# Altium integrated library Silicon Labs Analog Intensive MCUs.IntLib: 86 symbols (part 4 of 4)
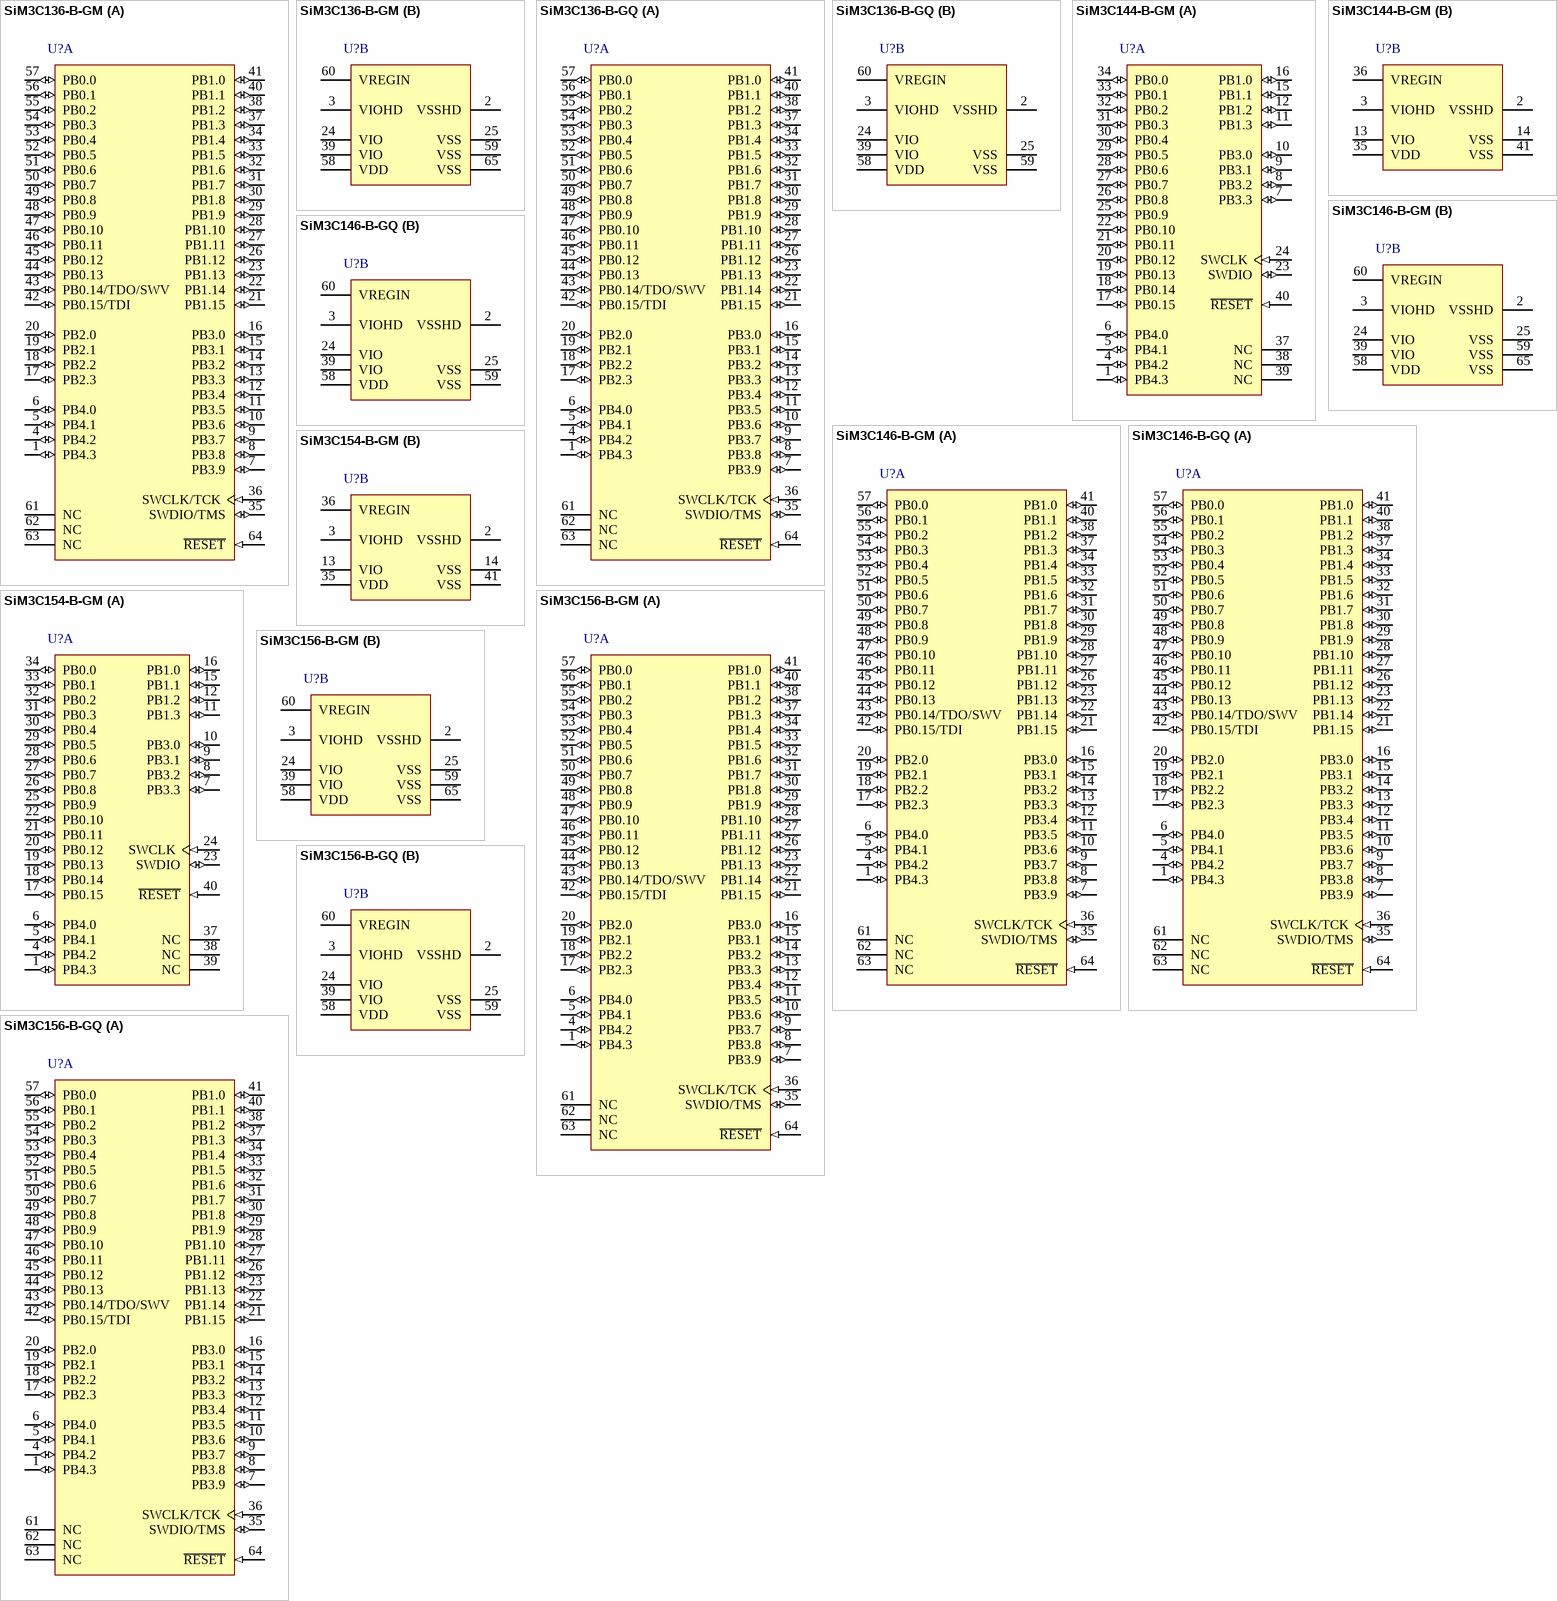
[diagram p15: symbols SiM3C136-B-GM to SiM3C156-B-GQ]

## SiM3C156-B-GM
designator U?
High-Performance, Low-Power, 32-Bit Precision32(TM) MCU Family, 80 MHz, 32 kB RAM, 128 kB Flash, -40 to 85 degC, 64-pin QFN; Manufacturer: Silicon Labs; PartNumber: SiM3C156-B-GM; ADC 1: 12-bit, 13-ch., 250 ksps; ADC 2: 12-bit, 15-ch., 250 ksps; AEC-Q100: FALSE; Comparators: 2; DAC: 10-bit, 2-ch.; Debug Interface: JTAG; SW; Dig I/O Pins: 50; Flash: 128 kB; Internal Osc. Accuracy: +/-1.5%; MCU Core: ARM Cortex-M3; MHz: 80; PCA Channels: 10; RAM: 32 kB; Temp Sensor: TRUE; Timers (16-bit): 4; Sub-Family: Analog Intensive MCUs
footprint SLAB-QFN-64-4100x4100TP_N (QFN, 64-Leads, Body 9x9mm, Pitch 0.5mm, Thermal Pad 4.1x4.1mm, IPC Medium Density)
footprint SLAB-QFN-64-4100x4100TP_L (QFN, 64-Leads, Body 9x9mm, Pitch 0.5mm, Thermal Pad 4.1x4.1mm, IPC High Density)
footprint SLAB-QFN-64-4100x4100TP_M (QFN, 64-Leads, Body 9x9mm, Pitch 0.5mm, Thermal Pad 4.1x4.1mm, IPC Low Density)
part A pins: 1 PB4.3 (io), 4 PB4.2 (io), 5 PB4.1 (io), 6 PB4.0 (io), 7 PB3.9 (io), 8 PB3.8 (io), 9 PB3.7 (io), 10 PB3.6 (io), 11 PB3.5 (io), 12 PB3.4 (io), 13 PB3.3 (io), 14 PB3.2 (io), 15 PB3.1 (io), 16 PB3.0 (io), 17 PB2.3 (io), 18 PB2.2 (io), 19 PB2.1 (io), 20 PB2.0 (io), 21 PB1.15 (io), 22 PB1.14 (io), 23 PB1.13 (io), 26 PB1.12 (io), 27 PB1.11 (io), 28 PB1.10 (io), 29 PB1.9 (io), 30 PB1.8 (io), 31 PB1.7 (io), 32 PB1.6 (io), 33 PB1.5 (io), 34 PB1.4 (io), 35 SWDIO/TMS (io), 36 SWCLK/TCK (in), 37 PB1.3 (io), 38 PB1.2 (io), 40 PB1.1 (io), 41 PB1.0 (io), 42 PB0.15/TDI (io), 43 PB0.14/TDO/SWV (io), 44 PB0.13 (io), 45 PB0.12 (io), 46 PB0.11 (io), 47 PB0.10 (io), 48 PB0.9 (io), 49 PB0.8 (io), 50 PB0.7 (io), 51 PB0.6 (io), 52 PB0.5 (io), 53 PB0.4 (io), 54 PB0.3 (io), 55 PB0.2 (io), 56 PB0.1 (io), 57 PB0.0 (io), 61 NC, 62 NC, 63 NC, 64 ~{RESET} (in)
part B pins: 2 VSSHD (power), 3 VIOHD (power), 24 VIO (power), 25 VSS (power), 39 VIO (power), 58 VDD (power), 59 VSS (power), 60 VREGIN (power), 65 VSS (power)

## SiM3C156-B-GQ
designator U?
High-Performance, Low-Power, 32-Bit Precision32(TM) MCU Family, 80 MHz, 32 kB RAM, 128 kB Flash, -40 to 85 degC, 64-pin QFP; Manufacturer: Silicon Labs; PartNumber: SiM3C156-B-GQ; ADC 1: 12-bit, 13-ch., 250 ksps; ADC 2: 12-bit, 15-ch., 250 ksps; AEC-Q100: FALSE; Comparators: 2; DAC: 10-bit, 2-ch.; Debug Interface: JTAG; SW; Dig I/O Pins: 50; Flash: 128 kB; Internal Osc. Accuracy: +/-1.5%; MCU Core: ARM Cortex-M3; MHz: 80; PCA Channels: 10; RAM: 32 kB; Temp Sensor: TRUE; Timers (16-bit): 4; Sub-Family: Analog Intensive MCUs
footprint SLAB-TQFP-64_N (QFP, 64-Leads, Body 10x10mm, Pitch 0.5mm, IPC Medium Density)
footprint SLAB-TQFP-64_L (QFP, 64-Leads, Body 10x10mm, Pitch 0.5mm, IPC High Density)
footprint SLAB-TQFP-64_M (QFP, 64-Leads, Body 10x10mm, Pitch 0.5mm, IPC Low Density)
part A pins: 1 PB4.3 (io), 4 PB4.2 (io), 5 PB4.1 (io), 6 PB4.0 (io), 7 PB3.9 (io), 8 PB3.8 (io), 9 PB3.7 (io), 10 PB3.6 (io), 11 PB3.5 (io), 12 PB3.4 (io), 13 PB3.3 (io), 14 PB3.2 (io), 15 PB3.1 (io), 16 PB3.0 (io), 17 PB2.3 (io), 18 PB2.2 (io), 19 PB2.1 (io), 20 PB2.0 (io), 21 PB1.15 (io), 22 PB1.14 (io), 23 PB1.13 (io), 26 PB1.12 (io), 27 PB1.11 (io), 28 PB1.10 (io), 29 PB1.9 (io), 30 PB1.8 (io), 31 PB1.7 (io), 32 PB1.6 (io), 33 PB1.5 (io), 34 PB1.4 (io), 35 SWDIO/TMS (io), 36 SWCLK/TCK (in), 37 PB1.3 (io), 38 PB1.2 (io), 40 PB1.1 (io), 41 PB1.0 (io), 42 PB0.15/TDI (io), 43 PB0.14/TDO/SWV (io), 44 PB0.13 (io), 45 PB0.12 (io), 46 PB0.11 (io), 47 PB0.10 (io), 48 PB0.9 (io), 49 PB0.8 (io), 50 PB0.7 (io), 51 PB0.6 (io), 52 PB0.5 (io), 53 PB0.4 (io), 54 PB0.3 (io), 55 PB0.2 (io), 56 PB0.1 (io), 57 PB0.0 (io), 61 NC, 62 NC, 63 NC, 64 ~{RESET} (in)
part B pins: 2 VSSHD (power), 3 VIOHD (power), 24 VIO (power), 25 VSS (power), 39 VIO (power), 58 VDD (power), 59 VSS (power), 60 VREGIN (power)

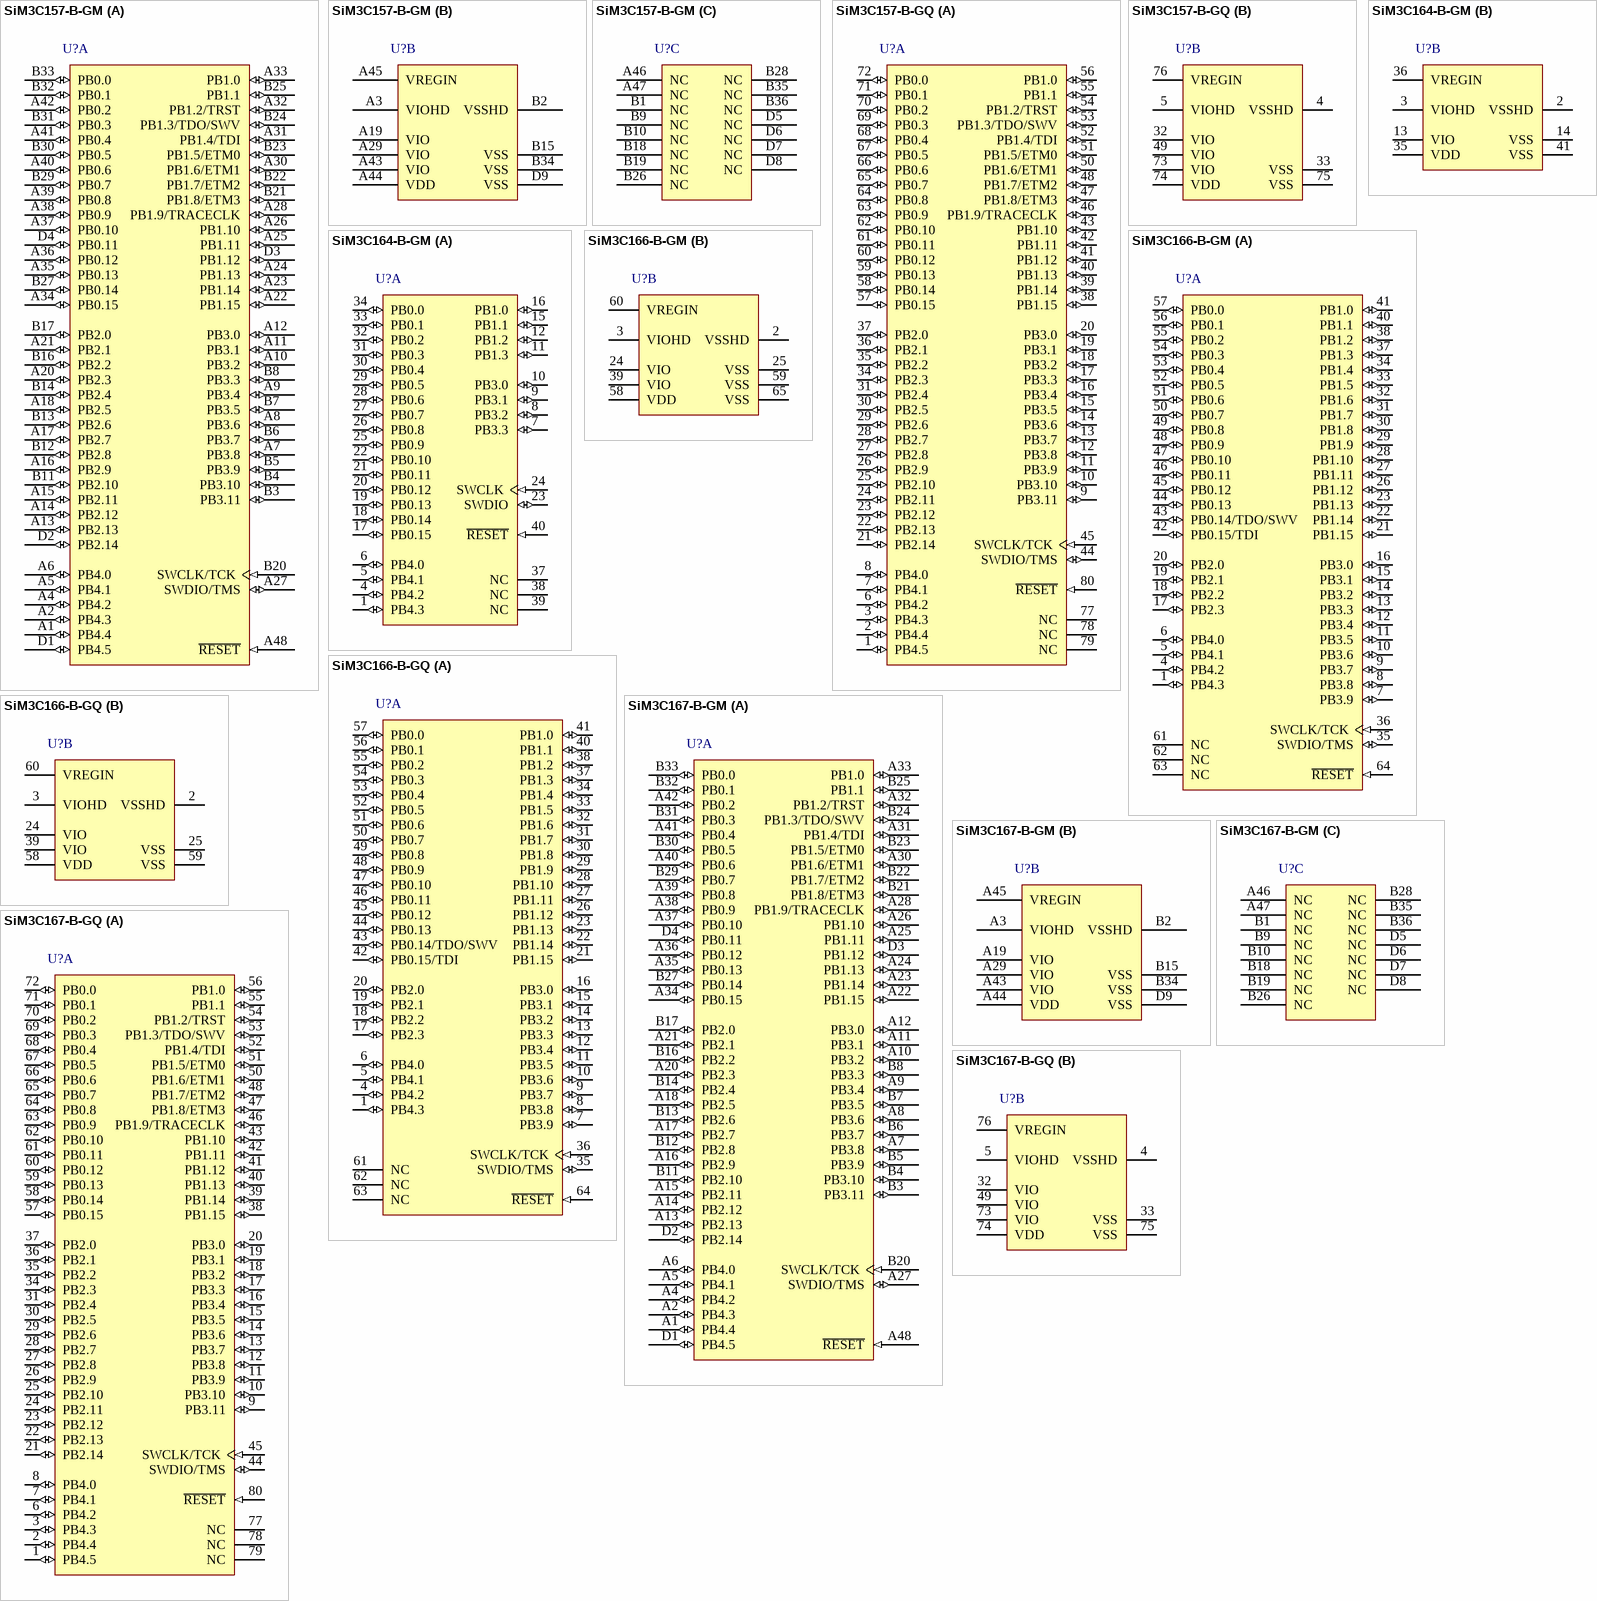
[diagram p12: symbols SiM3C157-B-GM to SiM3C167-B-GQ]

## SiM3C157-B-GM
designator U?
High-Performance, Low-Power, 32-Bit Precision32(TM) MCU Family, 80 MHz, 32 kB RAM, 128 kB Flash, -40 to 85 degC, 92-pin LGA; Manufacturer: Silicon Labs; PartNumber: SiM3C157-B-GM; ADC 1: 12-bit, 16-ch., 250 ksps; AEC-Q100: FALSE; Comparators: 2; DAC: 10-bit, 2-ch.; Debug Interface: ETM; JTAG; SW; Dig I/O Pins: 65; Flash: 128 kB; Internal Osc. Accuracy: +/-1.5%; MCU Core: ARM Cortex-M3; MHz: 80; PCA Channels: 10; RAM: 32 kB; Temp Sensor: TRUE; Timers (16-bit): 4; Sub-Family: Analog Intensive MCUs
footprint SLAB-LGA-92_V (LGA, 92-Leads, Body 7x7mm, Pitch 0.5mm, Thermal Pad 3.2x3.2mm)
part A pins: A1 PB4.4 (io), A2 PB4.3 (io), A4 PB4.2 (io), A5 PB4.1 (io), A6 PB4.0 (io), A7 PB3.8 (io), A8 PB3.6 (io), A9 PB3.4 (io), A10 PB3.2 (io), A11 PB3.1 (io), A12 PB3.0 (io), A13 PB2.13 (io), A14 PB2.12 (io), A15 PB2.11 (io), A16 PB2.9 (io), A17 PB2.7 (io), A18 PB2.5 (io), A20 PB2.3 (io), A21 PB2.1 (io), A22 PB1.15 (io), A23 PB1.14 (io), A24 PB1.13 (io), A25 PB1.11 (io), A26 PB1.10 (io), A27 SWDIO/TMS (io), A28 PB1.9/TRACECLK (io), A30 PB1.6/ETM1 (io), A31 PB1.4/TDI (io), A32 PB1.2/TRST (io), A33 PB1.0 (io), A34 PB0.15 (io), A35 PB0.13 (io), A36 PB0.12 (io), A37 PB0.10 (io), A38 PB0.9 (io), A39 PB0.8 (io), A40 PB0.6 (io), A41 PB0.4 (io), A42 PB0.2 (io), A48 ~{RESET} (in), B3 PB3.11 (io), B4 PB3.10 (io), B5 PB3.9 (io), B6 PB3.7 (io), B7 PB3.5 (io), B8 PB3.3 (io), B11 PB2.10 (io), B12 PB2.8 (io), B13 PB2.6 (io), B14 PB2.4 (io), B16 PB2.2 (io), B17 PB2.0 (io), B20 SWCLK/TCK (in), B21 PB1.8/ETM3 (io), B22 PB1.7/ETM2 (io), B23 PB1.5/ETM0 (io), B24 PB1.3/TDO/SWV (io), B25 PB1.1 (io), B27 PB0.14 (io), B29 PB0.7 (io), B30 PB0.5 (io), B31 PB0.3 (io), B32 PB0.1 (io), B33 PB0.0 (io), D1 PB4.5 (io), D2 PB2.14 (io), D3 PB1.12 (io), D4 PB0.11 (io)
part B pins: A3 VIOHD (power), A19 VIO (power), A29 VIO (power), A43 VIO (power), A44 VDD (power), A45 VREGIN (power), B2 VSSHD (power), B15 VSS (power), B34 VSS (power), D9 VSS (power)
part C pins: A46 NC, A47 NC, B1 NC, B9 NC, B10 NC, B18 NC, B19 NC, B26 NC, B28 NC, B35 NC, B36 NC, D5 NC, D6 NC, D7 NC, D8 NC

## SiM3C157-B-GQ
designator U?
High-Performance, Low-Power, 32-Bit Precision32(TM) MCU Family, 80 MHz, 32 kB RAM, 128 kB Flash, -40 to 85 degC, 80-pin QFP; Manufacturer: Silicon Labs; PartNumber: SiM3C157-B-GQ; ADC 1: 12-bit, 16-ch., 250 ksps; AEC-Q100: FALSE; Comparators: 2; DAC: 10-bit, 2-ch.; Debug Interface: ETM; JTAG; SW; Dig I/O Pins: 65; Flash: 128 kB; Internal Osc. Accuracy: +/-1.5%; MCU Core: ARM Cortex-M3; MHz: 80; PCA Channels: 10; RAM: 32 kB; Temp Sensor: TRUE; Timers (16-bit): 4; Sub-Family: Analog Intensive MCUs
footprint SLAB-TQFP-80_N (QFP, 80-Leads, Body 12x12mm, Pitch 0.5mm, IPC Medium Density)
footprint SLAB-TQFP-80_L (QFP, 80-Leads, Body 12x12mm, Pitch 0.5mm, IPC High Density)
footprint SLAB-TQFP-80_M (QFP, 80-Leads, Body 12x12mm, Pitch 0.5mm, IPC Low Density)
part A pins: 1 PB4.5 (io), 2 PB4.4 (io), 3 PB4.3 (io), 6 PB4.2 (io), 7 PB4.1 (io), 8 PB4.0 (io), 9 PB3.11 (io), 10 PB3.10 (io), 11 PB3.9 (io), 12 PB3.8 (io), 13 PB3.7 (io), 14 PB3.6 (io), 15 PB3.5 (io), 16 PB3.4 (io), 17 PB3.3 (io), 18 PB3.2 (io), 19 PB3.1 (io), 20 PB3.0 (io), 21 PB2.14 (io), 22 PB2.13 (io), 23 PB2.12 (io), 24 PB2.11 (io), 25 PB2.10 (io), 26 PB2.9 (io), 27 PB2.8 (io), 28 PB2.7 (io), 29 PB2.6 (io), 30 PB2.5 (io), 31 PB2.4 (io), 34 PB2.3 (io), 35 PB2.2 (io), 36 PB2.1 (io), 37 PB2.0 (io), 38 PB1.15 (io), 39 PB1.14 (io), 40 PB1.13 (io), 41 PB1.12 (io), 42 PB1.11 (io), 43 PB1.10 (io), 44 SWDIO/TMS (io), 45 SWCLK/TCK (in), 46 PB1.9/TRACECLK (io), 47 PB1.8/ETM3 (io), 48 PB1.7/ETM2 (io), 50 PB1.6/ETM1 (io), 51 PB1.5/ETM0 (io), 52 PB1.4/TDI (io), 53 PB1.3/TDO/SWV (io), 54 PB1.2/TRST (io), 55 PB1.1 (io), 56 PB1.0 (io), 57 PB0.15 (io), 58 PB0.14 (io), 59 PB0.13 (io), 60 PB0.12 (io), 61 PB0.11 (io), 62 PB0.10 (io), 63 PB0.9 (io), 64 PB0.8 (io), 65 PB0.7 (io), 66 PB0.6 (io), 67 PB0.5 (io), 68 PB0.4 (io), 69 PB0.3 (io), 70 PB0.2 (io), 71 PB0.1 (io), 72 PB0.0 (io), 77 NC, 78 NC, 79 NC, 80 ~{RESET} (in)
part B pins: 4 VSSHD (power), 5 VIOHD (power), 32 VIO (power), 33 VSS (power), 49 VIO (power), 73 VIO (power), 74 VDD (power), 75 VSS (power), 76 VREGIN (power)

## SiM3C164-B-GM
designator U?
High-Performance, Low-Power, 32-Bit Precision32(TM) MCU Family, 80 MHz, 32 kB RAM, 256 kB Flash, -40 to 85 degC, 40-pin QFN; Manufacturer: Silicon Labs; PartNumber: SiM3C164-B-GM; ADC 1: 12-bit, 7-ch., 250 ksps; ADC 2: 12-bit, 11-ch., 250 ksps; AEC-Q100: FALSE; Comparators: 2; DAC: 10-bit, 2-ch.; Debug Interface: SW; Dig I/O Pins: 28; Flash: 256 kB; Internal Osc. Accuracy: +/-1.5%; MCU Core: ARM Cortex-M3; MHz: 80; PCA Channels: 10; RAM: 32 kB; Temp Sensor: TRUE; Timers (16-bit): 4; Sub-Family: Analog Intensive MCUs
footprint SLAB-QFN-40-4500x4500TP_N (QFN, 40-Leads, Body 6x6mm, Pitch 0.5mm, Thermal Pad 4.5x4.5mm, IPC Medium Density)
footprint SLAB-QFN-40-4500x4500TP_L (QFN, 40-Leads, Body 6x6mm, Pitch 0.5mm, Thermal Pad 4.5x4.5mm, IPC High Density)
footprint SLAB-QFN-40-4500x4500TP_M (QFN, 40-Leads, Body 6x6mm, Pitch 0.5mm, Thermal Pad 4.5x4.5mm, IPC Low Density)
part A pins: 1 PB4.3 (io), 4 PB4.2 (io), 5 PB4.1 (io), 6 PB4.0 (io), 7 PB3.3 (io), 8 PB3.2 (io), 9 PB3.1 (io), 10 PB3.0 (io), 11 PB1.3 (io), 12 PB1.2 (io), 15 PB1.1 (io), 16 PB1.0 (io), 17 PB0.15 (io), 18 PB0.14 (io), 19 PB0.13 (io), 20 PB0.12 (io), 21 PB0.11 (io), 22 PB0.10 (io), 23 SWDIO (io), 24 SWCLK (in), 25 PB0.9 (io), 26 PB0.8 (io), 27 PB0.7 (io), 28 PB0.6 (io), 29 PB0.5 (io), 30 PB0.4 (io), 31 PB0.3 (io), 32 PB0.2 (io), 33 PB0.1 (io), 34 PB0.0 (io), 37 NC, 38 NC, 39 NC, 40 ~{RESET} (in)
part B pins: 2 VSSHD (power), 3 VIOHD (power), 13 VIO (power), 14 VSS (power), 35 VDD (power), 36 VREGIN (power), 41 VSS (power)

## SiM3C166-B-GM
designator U?
High-Performance, Low-Power, 32-Bit Precision32(TM) MCU Family, 80 MHz, 32 kB RAM, 256 kB Flash, -40 to 85 degC, 64-pin QFN; Manufacturer: Silicon Labs; PartNumber: SiM3C166-B-GM; ADC 1: 12-bit, 13-ch., 250 ksps; ADC 2: 12-bit, 15-ch., 250 ksps; AEC-Q100: FALSE; Comparators: 2; DAC: 10-bit, 2-ch.; Debug Interface: JTAG; SW; Dig I/O Pins: 50; Flash: 256 kB; Internal Osc. Accuracy: +/-1.5%; MCU Core: ARM Cortex-M3; MHz: 80; PCA Channels: 10; RAM: 32 kB; Temp Sensor: TRUE; Timers (16-bit): 4; Sub-Family: Analog Intensive MCUs
footprint SLAB-QFN-64-4100x4100TP_N (QFN, 64-Leads, Body 9x9mm, Pitch 0.5mm, Thermal Pad 4.1x4.1mm, IPC Medium Density)
footprint SLAB-QFN-64-4100x4100TP_L (QFN, 64-Leads, Body 9x9mm, Pitch 0.5mm, Thermal Pad 4.1x4.1mm, IPC High Density)
footprint SLAB-QFN-64-4100x4100TP_M (QFN, 64-Leads, Body 9x9mm, Pitch 0.5mm, Thermal Pad 4.1x4.1mm, IPC Low Density)
part A pins: 1 PB4.3 (io), 4 PB4.2 (io), 5 PB4.1 (io), 6 PB4.0 (io), 7 PB3.9 (io), 8 PB3.8 (io), 9 PB3.7 (io), 10 PB3.6 (io), 11 PB3.5 (io), 12 PB3.4 (io), 13 PB3.3 (io), 14 PB3.2 (io), 15 PB3.1 (io), 16 PB3.0 (io), 17 PB2.3 (io), 18 PB2.2 (io), 19 PB2.1 (io), 20 PB2.0 (io), 21 PB1.15 (io), 22 PB1.14 (io), 23 PB1.13 (io), 26 PB1.12 (io), 27 PB1.11 (io), 28 PB1.10 (io), 29 PB1.9 (io), 30 PB1.8 (io), 31 PB1.7 (io), 32 PB1.6 (io), 33 PB1.5 (io), 34 PB1.4 (io), 35 SWDIO/TMS (io), 36 SWCLK/TCK (in), 37 PB1.3 (io), 38 PB1.2 (io), 40 PB1.1 (io), 41 PB1.0 (io), 42 PB0.15/TDI (io), 43 PB0.14/TDO/SWV (io), 44 PB0.13 (io), 45 PB0.12 (io), 46 PB0.11 (io), 47 PB0.10 (io), 48 PB0.9 (io), 49 PB0.8 (io), 50 PB0.7 (io), 51 PB0.6 (io), 52 PB0.5 (io), 53 PB0.4 (io), 54 PB0.3 (io), 55 PB0.2 (io), 56 PB0.1 (io), 57 PB0.0 (io), 61 NC, 62 NC, 63 NC, 64 ~{RESET} (in)
part B pins: 2 VSSHD (power), 3 VIOHD (power), 24 VIO (power), 25 VSS (power), 39 VIO (power), 58 VDD (power), 59 VSS (power), 60 VREGIN (power), 65 VSS (power)

## SiM3C166-B-GQ
designator U?
High-Performance, Low-Power, 32-Bit Precision32(TM) MCU Family, 80 MHz, 32 kB RAM, 256 kB Flash, -40 to 85 degC, 64-pin QFP; Manufacturer: Silicon Labs; PartNumber: SiM3C166-B-GQ; ADC 1: 12-bit, 13-ch., 250 ksps; ADC 2: 12-bit, 15-ch., 250 ksps; AEC-Q100: FALSE; Comparators: 2; DAC: 10-bit, 2-ch.; Debug Interface: JTAG; SW; Dig I/O Pins: 50; Flash: 256 kB; Internal Osc. Accuracy: +/-1.5%; MCU Core: ARM Cortex-M3; MHz: 80; PCA Channels: 10; RAM: 32 kB; Temp Sensor: TRUE; Timers (16-bit): 4; Sub-Family: Analog Intensive MCUs
footprint SLAB-TQFP-64_N (QFP, 64-Leads, Body 10x10mm, Pitch 0.5mm, IPC Medium Density)
footprint SLAB-TQFP-64_L (QFP, 64-Leads, Body 10x10mm, Pitch 0.5mm, IPC High Density)
footprint SLAB-TQFP-64_M (QFP, 64-Leads, Body 10x10mm, Pitch 0.5mm, IPC Low Density)
part A pins: 1 PB4.3 (io), 4 PB4.2 (io), 5 PB4.1 (io), 6 PB4.0 (io), 7 PB3.9 (io), 8 PB3.8 (io), 9 PB3.7 (io), 10 PB3.6 (io), 11 PB3.5 (io), 12 PB3.4 (io), 13 PB3.3 (io), 14 PB3.2 (io), 15 PB3.1 (io), 16 PB3.0 (io), 17 PB2.3 (io), 18 PB2.2 (io), 19 PB2.1 (io), 20 PB2.0 (io), 21 PB1.15 (io), 22 PB1.14 (io), 23 PB1.13 (io), 26 PB1.12 (io), 27 PB1.11 (io), 28 PB1.10 (io), 29 PB1.9 (io), 30 PB1.8 (io), 31 PB1.7 (io), 32 PB1.6 (io), 33 PB1.5 (io), 34 PB1.4 (io), 35 SWDIO/TMS (io), 36 SWCLK/TCK (in), 37 PB1.3 (io), 38 PB1.2 (io), 40 PB1.1 (io), 41 PB1.0 (io), 42 PB0.15/TDI (io), 43 PB0.14/TDO/SWV (io), 44 PB0.13 (io), 45 PB0.12 (io), 46 PB0.11 (io), 47 PB0.10 (io), 48 PB0.9 (io), 49 PB0.8 (io), 50 PB0.7 (io), 51 PB0.6 (io), 52 PB0.5 (io), 53 PB0.4 (io), 54 PB0.3 (io), 55 PB0.2 (io), 56 PB0.1 (io), 57 PB0.0 (io), 61 NC, 62 NC, 63 NC, 64 ~{RESET} (in)
part B pins: 2 VSSHD (power), 3 VIOHD (power), 24 VIO (power), 25 VSS (power), 39 VIO (power), 58 VDD (power), 59 VSS (power), 60 VREGIN (power)

## SiM3C167-B-GM
designator U?
High-Performance, Low-Power, 32-Bit Precision32(TM) MCU Family, 80 MHz, 32 kB RAM, 256 kB Flash, -40 to 85 degC, 92-pin LGA; Manufacturer: Silicon Labs; PartNumber: SiM3C167-B-GM; ADC 1: 12-bit, 16-ch., 250 ksps; AEC-Q100: FALSE; Comparators: 2; DAC: 10-bit, 2-ch.; Debug Interface: ETM; JTAG; SW; Dig I/O Pins: 65; Flash: 256 kB; Internal Osc. Accuracy: +/-1.5%; MCU Core: ARM Cortex-M3; MHz: 80; PCA Channels: 10; RAM: 32 kB; Temp Sensor: TRUE; Timers (16-bit): 4; Sub-Family: Analog Intensive MCUs
footprint SLAB-LGA-92_V (LGA, 92-Leads, Body 7x7mm, Pitch 0.5mm, Thermal Pad 3.2x3.2mm)
part A pins: A1 PB4.4 (io), A2 PB4.3 (io), A4 PB4.2 (io), A5 PB4.1 (io), A6 PB4.0 (io), A7 PB3.8 (io), A8 PB3.6 (io), A9 PB3.4 (io), A10 PB3.2 (io), A11 PB3.1 (io), A12 PB3.0 (io), A13 PB2.13 (io), A14 PB2.12 (io), A15 PB2.11 (io), A16 PB2.9 (io), A17 PB2.7 (io), A18 PB2.5 (io), A20 PB2.3 (io), A21 PB2.1 (io), A22 PB1.15 (io), A23 PB1.14 (io), A24 PB1.13 (io), A25 PB1.11 (io), A26 PB1.10 (io), A27 SWDIO/TMS (io), A28 PB1.9/TRACECLK (io), A30 PB1.6/ETM1 (io), A31 PB1.4/TDI (io), A32 PB1.2/TRST (io), A33 PB1.0 (io), A34 PB0.15 (io), A35 PB0.13 (io), A36 PB0.12 (io), A37 PB0.10 (io), A38 PB0.9 (io), A39 PB0.8 (io), A40 PB0.6 (io), A41 PB0.4 (io), A42 PB0.2 (io), A48 ~{RESET} (in), B3 PB3.11 (io), B4 PB3.10 (io), B5 PB3.9 (io), B6 PB3.7 (io), B7 PB3.5 (io), B8 PB3.3 (io), B11 PB2.10 (io), B12 PB2.8 (io), B13 PB2.6 (io), B14 PB2.4 (io), B16 PB2.2 (io), B17 PB2.0 (io), B20 SWCLK/TCK (in), B21 PB1.8/ETM3 (io), B22 PB1.7/ETM2 (io), B23 PB1.5/ETM0 (io), B24 PB1.3/TDO/SWV (io), B25 PB1.1 (io), B27 PB0.14 (io), B29 PB0.7 (io), B30 PB0.5 (io), B31 PB0.3 (io), B32 PB0.1 (io), B33 PB0.0 (io), D1 PB4.5 (io), D2 PB2.14 (io), D3 PB1.12 (io), D4 PB0.11 (io)
part B pins: A3 VIOHD (power), A19 VIO (power), A29 VIO (power), A43 VIO (power), A44 VDD (power), A45 VREGIN (power), B2 VSSHD (power), B15 VSS (power), B34 VSS (power), D9 VSS (power)
part C pins: A46 NC, A47 NC, B1 NC, B9 NC, B10 NC, B18 NC, B19 NC, B26 NC, B28 NC, B35 NC, B36 NC, D5 NC, D6 NC, D7 NC, D8 NC

## SiM3C167-B-GQ
designator U?
High-Performance, Low-Power, 32-Bit Precision32(TM) MCU Family, 80 MHz, 32 kB RAM, 256 kB Flash, -40 to 85 degC, 80-pin QFP; Manufacturer: Silicon Labs; PartNumber: SiM3C167-B-GQ; ADC 1: 12-bit, 16-ch., 250 ksps; AEC-Q100: FALSE; Comparators: 2; DAC: 10-bit, 2-ch.; Debug Interface: ETM; JTAG; SW; Dig I/O Pins: 65; Flash: 256 kB; Internal Osc. Accuracy: +/-1.5%; MCU Core: ARM Cortex-M3; MHz: 80; PCA Channels: 10; RAM: 32 kB; Temp Sensor: TRUE; Timers (16-bit): 4; Sub-Family: Analog Intensive MCUs
footprint SLAB-TQFP-80_N (QFP, 80-Leads, Body 12x12mm, Pitch 0.5mm, IPC Medium Density)
footprint SLAB-TQFP-80_L (QFP, 80-Leads, Body 12x12mm, Pitch 0.5mm, IPC High Density)
footprint SLAB-TQFP-80_M (QFP, 80-Leads, Body 12x12mm, Pitch 0.5mm, IPC Low Density)
part A pins: 1 PB4.5 (io), 2 PB4.4 (io), 3 PB4.3 (io), 6 PB4.2 (io), 7 PB4.1 (io), 8 PB4.0 (io), 9 PB3.11 (io), 10 PB3.10 (io), 11 PB3.9 (io), 12 PB3.8 (io), 13 PB3.7 (io), 14 PB3.6 (io), 15 PB3.5 (io), 16 PB3.4 (io), 17 PB3.3 (io), 18 PB3.2 (io), 19 PB3.1 (io), 20 PB3.0 (io), 21 PB2.14 (io), 22 PB2.13 (io), 23 PB2.12 (io), 24 PB2.11 (io), 25 PB2.10 (io), 26 PB2.9 (io), 27 PB2.8 (io), 28 PB2.7 (io), 29 PB2.6 (io), 30 PB2.5 (io), 31 PB2.4 (io), 34 PB2.3 (io), 35 PB2.2 (io), 36 PB2.1 (io), 37 PB2.0 (io), 38 PB1.15 (io), 39 PB1.14 (io), 40 PB1.13 (io), 41 PB1.12 (io), 42 PB1.11 (io), 43 PB1.10 (io), 44 SWDIO/TMS (io), 45 SWCLK/TCK (in), 46 PB1.9/TRACECLK (io), 47 PB1.8/ETM3 (io), 48 PB1.7/ETM2 (io), 50 PB1.6/ETM1 (io), 51 PB1.5/ETM0 (io), 52 PB1.4/TDI (io), 53 PB1.3/TDO/SWV (io), 54 PB1.2/TRST (io), 55 PB1.1 (io), 56 PB1.0 (io), 57 PB0.15 (io), 58 PB0.14 (io), 59 PB0.13 (io), 60 PB0.12 (io), 61 PB0.11 (io), 62 PB0.10 (io), 63 PB0.9 (io), 64 PB0.8 (io), 65 PB0.7 (io), 66 PB0.6 (io), 67 PB0.5 (io), 68 PB0.4 (io), 69 PB0.3 (io), 70 PB0.2 (io), 71 PB0.1 (io), 72 PB0.0 (io), 77 NC, 78 NC, 79 NC, 80 ~{RESET} (in)
part B pins: 4 VSSHD (power), 5 VIOHD (power), 32 VIO (power), 33 VSS (power), 49 VIO (power), 73 VIO (power), 74 VDD (power), 75 VSS (power), 76 VREGIN (power)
